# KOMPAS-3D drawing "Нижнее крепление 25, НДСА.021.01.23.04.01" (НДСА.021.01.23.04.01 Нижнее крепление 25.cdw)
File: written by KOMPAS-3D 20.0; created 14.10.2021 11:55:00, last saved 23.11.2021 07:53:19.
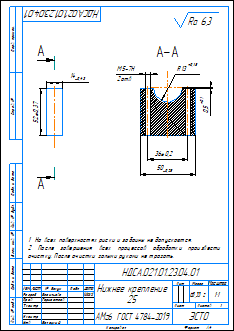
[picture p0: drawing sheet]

Sheet 1: A4, portrait

Document properties: Полное имя файла: C:\Users\s.pischagina\Desktop\PLM\НДСА.021.01.23.04.01 Нижнее крепление 25.cdw; Автор: adminzsc; Параметр неуказанной шероховатости: Ra 6,3; Масса: 0.065326; 281289132031: <item xmlns="http://appius.ru/pdm" xmlns:xs="http://www.w3.org/2001/XMLSchema" xmlns:xsi="http://www.w3.org/2001/XMLSchema-instance" xsi:type="item">  <element xmlns:d2p1="http://v8.1c.ru/8.1/data/enterprise/current-config" xsi:type="d2p1:CatalogRef.aps_Элемен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; 281289132231: <item xmlns="http://appius.ru/pdm" xmlns:xs="http://www.w3.org/2001/XMLSchema" xmlns:xsi="http://www.w3.org/2001/XMLSchema-instance" xsi:type="item">  <element xmlns:d2p1="http://v8.1c.ru/8.1/data/enterprise/current-config" xsi:type="d2p1:CatalogRef.aps_Элемен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; PDM_DOCXDTO: <item xmlns="http://appius.ru/pdm" xmlns:xs="http://www.w3.org/2001/XMLSchema" xmlns:xsi="http://www.w3.org/2001/XMLSchema-instance" xsi:type="item">  <element xmlns:d2p1="http://v8.1c.ru/8.1/data/enterprise/current-config" xsi:type="d2p1:CatalogRef.aps_Элемен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; PDM_ITEMXDTO: <item xmlns="http://appius.ru/pdm" xmlns:xs="http://www.w3.org/2001/XMLSchema" xmlns:xsi="http://www.w3.org/2001/XMLSchema-instance" xsi:type="item">  <element xmlns:d2p1="http://v8.1c.ru/8.1/data/enterprise/current-config" xsi:type="d2p1:CatalogRef.aps_Элемен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; PDM_DRAWINGXDTO: <item xmlns="http://appius.ru/pdm" xmlns:xs="http://www.w3.org/2001/XMLSchema" xmlns:xsi="http://www.w3.org/2001/XMLSchema-instance" xsi:type="item">  <element xmlns:d2p1="http://v8.1c.ru/8.1/data/enterprise/current-config" xsi:type="d2p1:CatalogRef.aps_Элемен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

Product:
- Part/product: Нижнее крепление 25  | designation НДСА.021.01.23.04.01
    Материал: АМг6  ГОСТ 4784-2019 (density 2640 kg/m3)
    Масса: 0.065326
    additional columns: <item xmlns="http://appius.ru/pdm" xmlns:xs="http://www.w3.org/2001/XMLSchema" x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; <item xmlns="http://appius.ru/pdm" xmlns:xs="http://www.w3.org/2001/XMLSchema" x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; <item xmlns="http://appius.ru/pdm" xmlns:xs="http://www.w3.org/2001/XMLSchema" x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; <item xmlns="http://appius.ru/pdm" xmlns:xs="http://www.w3.org/2001/XMLSchema" x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; <item xmlns="http://appius.ru/pdm" xmlns:xs="http://www.w3.org/2001/XMLSchema" x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
    source file: НДСА.021.01.23.04.01 Нижнее крепление 25.cdw

Title block, sheet 1: Наименование: Нижнее крепление / 25; designation: НДСА.021.01.23.04.01; Материал: АМг6  ГОСТ 4784-2019; Масса: 65,33 г; Количество листов документа: 1; organisation: ЭСТО; Форматы листов документа: A4; stored path: C:\Users\vasilyeva\Desktop\PM_APPIUS\НДСА.021.01.23.04.01 Нижнее крепление 25.cdw; Разработал: Васильева; Проверил: Горностаев; Утвердил: Белецкий; Разработал, date: 14.10.2021

Views: Вид 1, Слева, Разрез А-А
Referenced files in C:\Users\vasilyeva\Desktop\PM_APPIUS\: НДСА.021.01.23.04.01 Нижнее крепление 25.m3d
Referenced files in C:\Users\s.pischagina\Desktop\PLM\: НДСА.021.01.23.04.01 Нижнее крепление 25.m3d
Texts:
  Ra 6,3
  НДСА.021.01.23.04.01 Нижнее крепление 25
Dimensions and other numbers on the sheet: 14; 52±0,37; 50; 36±0,2; 13; 0,5; -7Н; 5; 2отв; 1:1; 1; 25; 65,33 г; 14.10.2021

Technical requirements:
  1  На всех поверхностях риски и забоины не допускаются.
  2 После завершения всех процессов обработки произвести
  очистку. После очистки голыми руками не трогать.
